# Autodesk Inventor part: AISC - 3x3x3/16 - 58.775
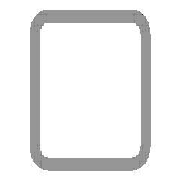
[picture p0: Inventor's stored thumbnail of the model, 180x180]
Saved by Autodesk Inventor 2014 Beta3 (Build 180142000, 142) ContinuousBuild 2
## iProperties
_CCFamilyMember: 9
_CCFamilyDisplayName: ANSI AISC (Square) - Tube
_FrameMemberDoc: Frame Member File
_Version: 15.0.0
_GetPNFromCC: 1
Created: 2011-01
Part Number: AISC - 3x3x3/16 - 58.775
Material: Steel, Mild
Description: Tube
Document SubType Name: Modeling
Standard: ANSI
Designer: Beta-8540w
Standards Organization: ANSI
Language: en-US
Size Designation: 3x3x3/16
Categories: <MemberInstance><Categories><Category DisplayName="Structural Shapes" InternalName="089c4875-fa83-4c05-b084-43b9cc11f5ed" Mnemonic="GRDR"><CategoryParameter Dis
Stock Number: 3x3x3/16
Density: 7.86 g/cm^3
Appearance: Steel
IsCustomPart: 1
G_L: 58.775 in
G_W: 3.000 in
G_H: 3.000 in
+1EAFC555-4950-48CB-9237-33026613FA03+CUTDETAIL1: Cut
Author: Beta-8540w
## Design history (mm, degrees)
node "Start plane"
node "End plane"
sketch "Sketch"
  geometry: L1 (-38.1, -28.575)-(-38.1, 28.575); L2 (-28.575, 38.1)-(28.575, 38.1); L3 (38.1, 28.575)-(38.1, -28.575); L4 (28.575, -38.1)-(-28.575, -38.1); L5 (-28.575, 33.337)-(28.575, 33.338); L6 (33.338, 28.575)-(33.338, -28.575); L7 (28.575, -33.337)-(-28.575, -33.338); L8 (-33.338, -28.575)-(-33.338, 28.575); L9 (0, 56.102)-(0, -56.102) reference; L10 (-56.102, 0)-(56.102, 0) reference; A1 r 9.525 centre (-28.575, -28.575) between (-38.1, -28.575) and (-28.575, -38.1); A2 r 9.525 centre (-28.575, 28.575) between (-28.575, 38.1) and (-38.1, 28.575); A3 r 9.525 centre (28.575, 28.575) between (38.1, 28.575) and (28.575, 38.1); A4 r 9.525 centre (28.575, -28.575) between (28.575, -38.1) and (38.1, -28.575); A5 r 4.763 centre (-28.575, 28.575) between (-28.575, 33.337) and (-33.338, 28.575); A6 r 4.763 centre (28.575, 28.575) between (33.338, 28.575) and (28.575, 33.338); A7 r 4.763 centre (28.575, -28.575) between (28.575, -33.337) and (33.338, -28.575); A8 r 4.763 centre (-28.575, -28.575) between (-33.338, -28.575) and (-28.575, -33.338)
  constraints: 16 end point, 16 point on circle, 8 centre point, 8 tangent, 4 parallel, 3 equal radius, 2 perpendicular, 7 other
  dimensions: "d10" = 76.2 distance between parallel lines of L2 L4 (= G_H); "d11" = 76.2 distance between parallel lines of L1 L3 (= G_W); "d12" = 4.7625 distance between parallel lines of L3 L6 (= G_T); "d15" = 38.1 distance between parallel lines of L2 L10 (= 0.5 x d10); "d16" = 38.1 distance between parallel lines of L9 L3 (= 0.5 x d11); "d17" = 9.525 radius of A1 (= G_IR)
extrude "Body" new body sketch "Sketch" stored distance "d3" = 1492.89148 (= G_L); taper "d4" = 0 deg
node "Driven Length"
  sketch "Sketch3"
    geometry: L1 (0, 0)-(10, 0) reference
    constraints: 2 end point, 1 horizontal
  workplane "Work Plane3"
  sketch "Sketch4"
    geometry: L1 (-2, 31.109)-(12, 31.109) reference; L2 (-2, 1524)-(12, 1524) reference
    dimensions: "d19" = 1492.89148 distance between parallel lines of L1 L2 (derived)
workplane "Work Plane4"
split "Split1"
body "Solid1"
other parameters: "G_W" = 76.2 [user parameter; used in 1 equation term], "G_H" = 76.2 [user parameter; used in 1 equation term], "G_T" = 4.7625 [user parameter; used in 1 equation term], "G_IR" = 9.525 [user parameter; used in 1 equation term], "G_L" = 1492.89148 (= d19) [user parameter; used in 1 equation term], "G_OFFSET_START" = -31.10852 [user parameter; used in 1 equation term], "G_OFFSET_END" = 0 [user parameter; used in 1 equation term], "d13" = 31.10852 (= -G_OFFSET_START), "d14" = 1524 (= G_OFFSET_END + B_L), "B_L" = 1524 [user parameter; used in 1 equation term], "d18" = 90 deg
